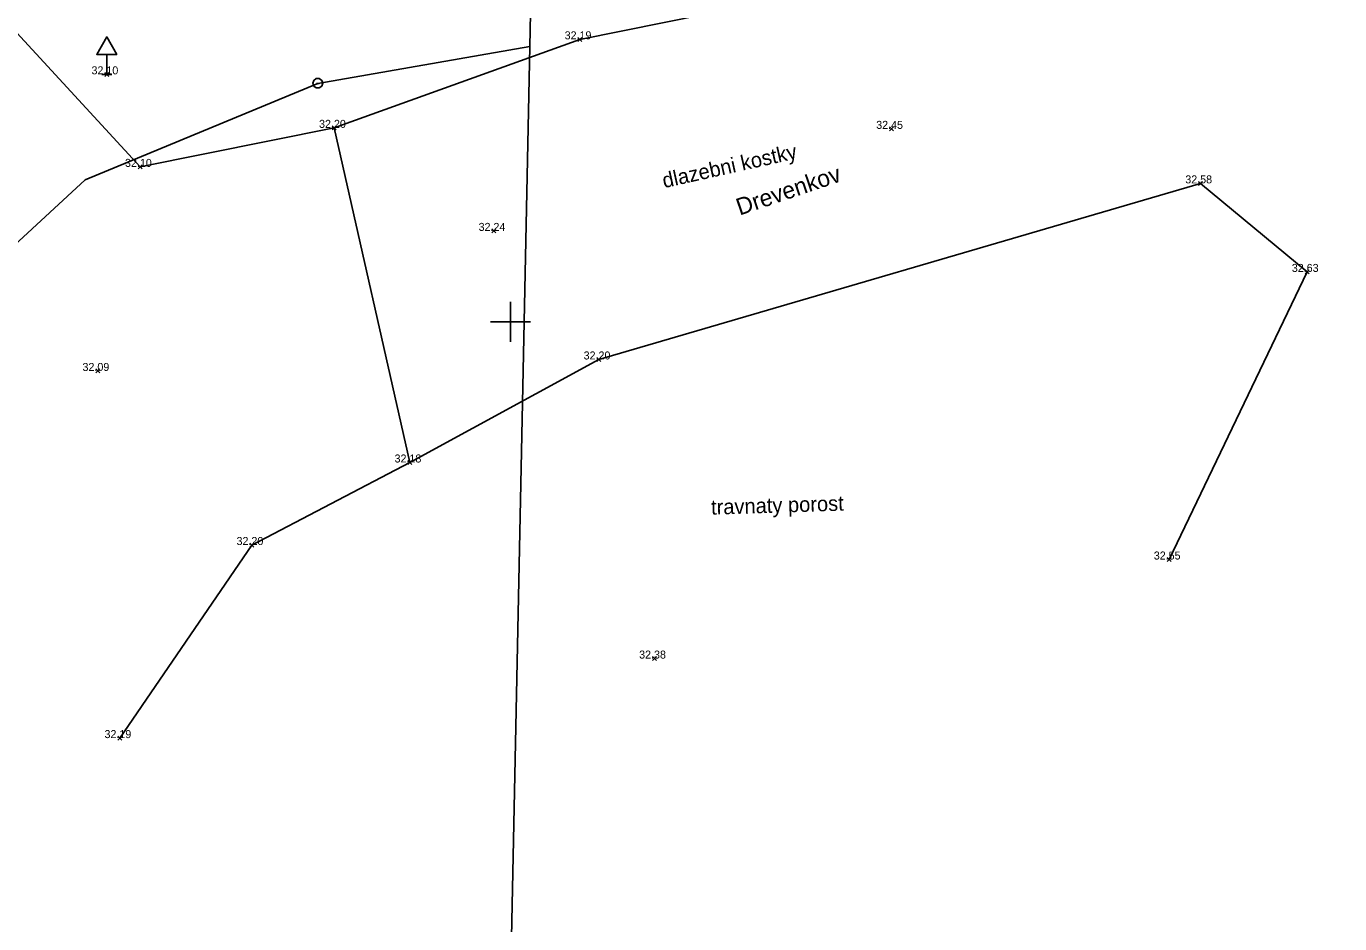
# Model space of a CAD drawing. Extents: x -772865 to -772533, y -1034366 to -1034132.
# Drawn here: x -772834.68 to -772808.42, y -1034312.03 to -1034294.09 of the extents above; entities that cross this region are included whole.
import ezdxf

# ---------------------------------------------------------------- set-up
doc = ezdxf.new("R2010")
doc.units = 0
for name, color, linetype in [('body', 7, 'Continuous'), ('dopravni_znacky', 7, 'Continuous'), ('KM_hranice', 7, 'Continuous'), ('KM_mezni_znaky', 7, 'Continuous'), ('KM_popis', 7, 'Continuous'), ('mistni_popis', 7, 'Continuous'), ('oddeleni_ploch', 7, 'Continuous'), ('souradnicova_sit', 7, 'Continuous'), ('vyskove_koty', 7, 'Continuous')]:
    doc.layers.add(name, color=color, linetype=linetype)

msp = doc.modelspace()

# ---------------------------------------------------------------- linework, layer by layer
at = {"layer": 'body'}
for p, q in [((-772823.57, -1034294.39), (-772823.65, -1034294.31)), ((-772823.65, -1034294.39), (-772823.57, -1034294.31)), ((-772833.03, -1034295.09), (-772833.11, -1034295.01)), ((-772833.11, -1034295.09), (-772833.03, -1034295.01)), ((-772828.48, -1034296.16), (-772828.56, -1034296.08)), ((-772828.56, -1034296.16), (-772828.48, -1034296.08)), ((-772817.34, -1034296.18), (-772817.42, -1034296.1)), ((-772817.42, -1034296.18), (-772817.34, -1034296.1)), ((-772832.36, -1034296.94), (-772832.44, -1034296.86)), ((-772832.44, -1034296.94), (-772832.36, -1034296.86)), ((-772811.16, -1034297.27), (-772811.24, -1034297.19)), ((-772811.24, -1034297.27), (-772811.16, -1034297.19)), ((-772825.29, -1034298.22), (-772825.37, -1034298.14)), ((-772825.37, -1034298.22), (-772825.29, -1034298.14)), ((-772809.03, -1034299.04), (-772809.11, -1034298.96)), ((-772809.11, -1034299.04), (-772809.03, -1034298.96)), ((-772823.19, -1034300.79), (-772823.27, -1034300.71)), ((-772823.27, -1034300.79), (-772823.19, -1034300.71)), ((-772833.21, -1034301.02), (-772833.29, -1034300.94)), ((-772833.29, -1034301.02), (-772833.21, -1034300.94)), ((-772826.97, -1034302.85), (-772827.05, -1034302.77)), ((-772827.05, -1034302.85), (-772826.97, -1034302.77)), ((-772830.13, -1034304.5), (-772830.21, -1034304.42)), ((-772830.21, -1034304.5), (-772830.13, -1034304.42)), ((-772811.79, -1034304.79), (-772811.87, -1034304.71)), ((-772811.87, -1034304.79), (-772811.79, -1034304.71)), ((-772822.08, -1034306.77), (-772822.16, -1034306.69)), ((-772822.16, -1034306.77), (-772822.08, -1034306.69)), ((-772832.77, -1034308.36), (-772832.85, -1034308.28)), ((-772832.85, -1034308.36), (-772832.77, -1034308.28))]:
    msp.add_line(p, q, dxfattribs=at)
at = {"layer": 'dopravni_znacky'}
msp.add_line((-772833.17, -1034295.05), (-772832.97, -1034295.05), dxfattribs=at)
msp.add_lwpolyline([(-772833.07, -1034295.05), (-772833.07, -1034294.65), (-772832.87, -1034294.65), (-772833.07, -1034294.3), (-772833.27, -1034294.65), (-772833.07, -1034294.65)], dxfattribs=at)
at = {"layer": 'KM_hranice'}
for p, q in [((-772824.57, -1034292.42), (-772824.61, -1034294.49)), ((-772828.85, -1034295.23), (-772824.61, -1034294.49)), ((-772825.31, -1034328.46), (-772824.61, -1034294.49)), ((-772833.5, -1034297.16), (-772828.85, -1034295.23)), ((-772838.02, -1034301.32), (-772833.5, -1034297.16))]:
    msp.add_line(p, q, dxfattribs=at)
at = {"layer": 'KM_mezni_znaky'}
msp.add_line((-772828.874, -1034295.23), (-772828.826, -1034295.23), dxfattribs=at)
msp.add_lwpolyline([(-772828.82, -1034295.134), (-772828.77, -1034295.17), (-772828.75, -1034295.228), (-772828.77, -1034295.286), (-772828.82, -1034295.322), (-772828.882, -1034295.322), (-772828.932, -1034295.286), (-772828.952, -1034295.228), (-772828.932, -1034295.17), (-772828.882, -1034295.134)], close=True, dxfattribs=at)
at = {"layer": 'oddeleni_ploch'}
for points in [[(-772569.67, -1034207.72), (-772578.35, -1034211.18), (-772588.33, -1034216.15), (-772592.11, -1034217.46), (-772598.89, -1034219.1), (-772610.21, -1034219.57), (-772621.14, -1034219.48), (-772637.34, -1034221.06), (-772647.54, -1034222.08), (-772674.34, -1034233.24), (-772685.01, -1034239.21), (-772697.33, -1034242.95), (-772712.12, -1034249.56), (-772725.85, -1034254.8), (-772738.85, -1034261.98), (-772750.37, -1034267.76), (-772764, -1034272.65), (-772783.9, -1034280.59), (-772796.38, -1034286.28), (-772810.31, -1034291.67), (-772823.61, -1034294.35), (-772828.52, -1034296.12), (-772827.01, -1034302.81), (-772823.23, -1034300.75)], [(-772828.52, -1034296.12), (-772832.4, -1034296.9), (-772836.65, -1034292.29), (-772840.28, -1034293.19), (-772840.9, -1034289.55)], [(-772811.83, -1034304.75), (-772809.07, -1034299), (-772811.2, -1034297.23), (-772823.23, -1034300.75)], [(-772827.01, -1034302.81), (-772830.17, -1034304.46), (-772832.81, -1034308.32)]]:
    msp.add_lwpolyline(points, dxfattribs=at)
at = {"layer": 'souradnicova_sit'}
for p, q in [((-772825, -1034299.6), (-772825, -1034300.4)), ((-772825.4, -1034300), (-772824.6, -1034300))]:
    msp.add_line(p, q, dxfattribs=at)

# ---------------------------------------------------------------- texts
at = {"layer": 'KM_popis'}
msp.add_text('Drevenkov', height=0.34, rotation=18.6784, dxfattribs=at).set_placement((-772820.416, -1034297.875))
at = {"layer": 'mistni_popis'}
for s, rotation, p in [('dlazebni kostky', 12.6051, (-772821.925, -1034297.326)), ('travnaty porost', 1.7762, (-772820.983, -1034303.854))]:
    msp.add_text(s, height=0.3, rotation=rotation, dxfattribs=at).set_placement(p)
at = {"layer": 'vyskove_koty'}
for s, p in [('32.19', (-772823.915, -1034294.35)), ('32.10', (-772833.375, -1034295.05)), ('32.20', (-772828.825, -1034296.12)), ('32.45', (-772817.685, -1034296.14)), ('32.10', (-772832.705, -1034296.9)), ('32.58', (-772811.505, -1034297.23)), ('32.24', (-772825.635, -1034298.18)), ('32.63', (-772809.375, -1034299)), ('32.20', (-772823.535, -1034300.75)), ('32.09', (-772833.555, -1034300.98)), ('32.18', (-772827.315, -1034302.81)), ('32.20', (-772830.475, -1034304.46)), ('32.55', (-772812.135, -1034304.75)), ('32.38', (-772822.425, -1034306.73)), ('32.19', (-772833.115, -1034308.32))]:
    msp.add_text(s, height=0.16, dxfattribs=at).set_placement(p)

doc.saveas('drawing.dxf')
